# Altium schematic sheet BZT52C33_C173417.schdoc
size 127 x 101 mm
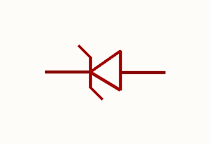
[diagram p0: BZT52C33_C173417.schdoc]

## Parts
D?  bzt52c33_c173417  [SOD-123_L2.7-W1.6-LS3.7-RD]  (value not drawn)

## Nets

Not connected (* = marked no-connect by the designer): D? 1(C) 2(A)

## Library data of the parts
D? = bzt52c33_c173417: 二极管配置:1个独立式;稳压值(标称值):33V;稳压值(范围):31.35V~34.65V;耗散功率(Pd):500mW;; Manufacturer: MDD(辰达半导体); AddInBom: yes; ModelId: ad7e39f9e5534b3c96ffdc5532ebb493; ModelName: SOD-123_L2.7-W1.6-H1.4-LS3.7; ModelTransform: 146.026,62.992,0,180,0,0,0.0005,0,0; Diode Configuration: 1个独立式; Zener Voltage(Nom): 33V; Reverse Leakage Current (Ir): 100nA@25V; Pd - Power Dissipation: 500mW; Impedance(Zzt): 80Ω; Tolerance: ±5%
